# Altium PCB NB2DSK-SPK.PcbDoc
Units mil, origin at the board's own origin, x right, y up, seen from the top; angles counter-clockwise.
Board outline 10614.17 x 2937.01 mil, 2 copper layers (Top Layer, Bottom Layer); 27 components, 35 nets, 104 pads, 52 vias.
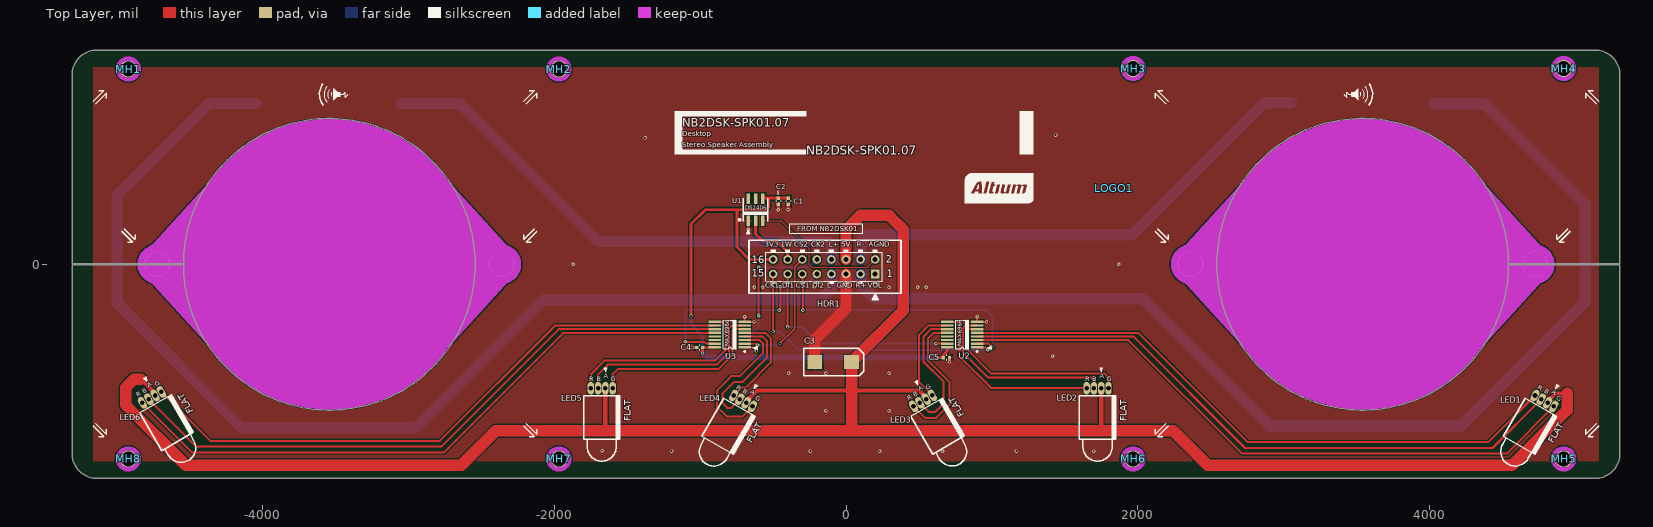
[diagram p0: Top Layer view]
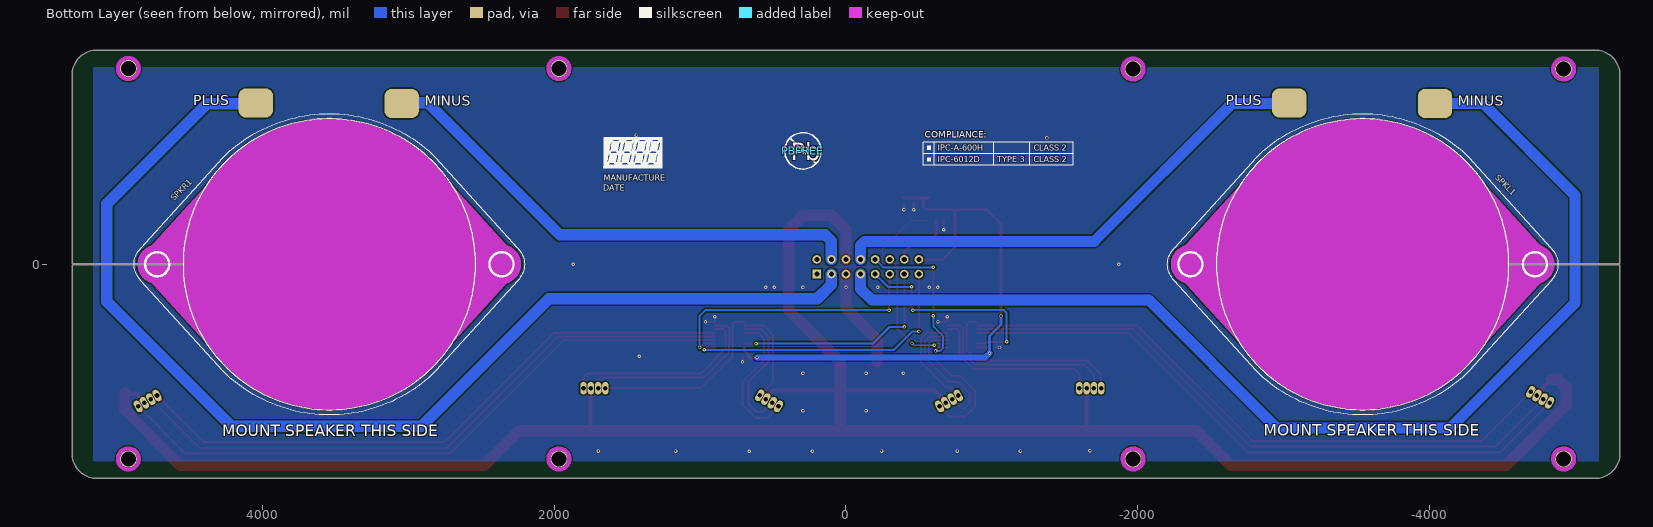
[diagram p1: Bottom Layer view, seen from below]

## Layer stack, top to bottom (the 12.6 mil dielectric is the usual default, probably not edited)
Top Layer: signal copper 1.4
Dielectric: core 12.6, FR-4, Dk 4.8
Bottom Layer: signal copper 1.4

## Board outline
-5137.8,-1468.51 cw(c-5137.8,-1299.21) -5307.09,-1299.21 -5307.09,-3.94 -4543.31,-3.94 -4543.3,-3.9 ccw(c-3543.31,0) -4543.3,3.92 -4543.31,3.92 -5307.09,3.92 -5307.09,1299.21 cw(c-5137.8,1299.21) -5137.8,1468.5 5137.8,1468.5 cw(c5137.8,1299.21) 5307.09,1299.21 5307.09,3.92 4543.31,3.92 4543.3,3.92 ccw(c3543.31,0.02) 4543.3,-3.9 4543.31,-3.94 5307.09,-3.94 5307.09,-1299.21 cw(c5137.8,-1299.21) 5137.8,-1468.51

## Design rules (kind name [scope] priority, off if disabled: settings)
Clearance "Pad-Pad Clearance Same Net" [IsPad vs IsPad] p1 off: gap=3.94
Clearance "General Clearance" [All] p2: gap=5
ComponentClearance [All] p1 off: gap=7.87 collisioncheckmode=3 verticalgap=10 showdistances=FALSE
DiffPairsRouting [All] p1: maxlimit=5 minlimit=5 mostfreqgap=5 maxuncoupledlength=200
FabricationTestPointUsage TestPointUsage [All] p1 off: valid=0 allowmultiple=FALSE
FabricationTestpoint Testpoint [All] p1 off: side=3 testpointundercomponent=TRUE minsize=40 maxsize=100 preferedsize=60 minholesize=0 maxholesize=40 preferedholesize=32 testpointgrid=1 allowsidetop=TRUE allowsidebottom=TRUE usegrid=TRUE gridtolerance=0.01
HoleSize [All] p1: absolutevalues=TRUE maxlimit=204.72 minlimit=7.87 maxpercent=80.000 minpercent=20.000
MatchedLengths DiffPair_MatchedLengths [(IsDifferentialPair And (Name = 'DIFF_RX1'))] p1: tolerance=1000 checknetsindiffpair=TRUE checkdiffpairvsdiffpair=TRUE checkothers=TRUE
MinimumAnnularRing [All] p1: minimumring=4.72
PlaneClearance [All] p1: clearance=11.81
PlaneConnect [All] p1: planeconnectstyle=Direct reliefexpansion=19.68 reliefentries=4 reliefconductorwidth=9.84 reliefairgap=9.84
PolygonConnect PolygonConnect_Tight [IsVia] p1: connectstyle=Direct reliefconductorwidth=11.81 reliefentries=4 polygonreliefangle="90 Angle"
PolygonConnect "PolygonConnect - Heatsink" [(HasFootprint('TO-263') AND InNet('VCCINT'))] p2: connectstyle=Relief reliefconductorwidth=10 reliefentries=4 polygonreliefangle="90 Angle"
PolygonConnect [IsPAD] p3: connectstyle=Relief reliefconductorwidth=11.81 reliefentries=4 polygonreliefangle="90 Angle"
RoutingLayers [All] p1: top layer_v5=FALSE bottom layer_v5=FALSE
RoutingVias [All] p1: holewidth=11.81 width=23.62 viastyle="Through Hole" minholewidth=11.81 minwidth=23.62 maxholewidth=19.68 maxwidth=35.43
ShortCircuit ShortCircuit_1 [Net = 'No Net' vs Net = 'No Net'] p1: allowed=TRUE
ShortCircuit [All] p2: allowed=FALSE
SilkscreenOverComponentPads [All] p1: minsilkscreentomaskgap=10
SolderMaskExpansion SolderMaskExpansion_Vias [IsVia] p1: expansion=-25.59
SolderMaskExpansion [All] p2: expansion=2.01
Width [All] p1: maxlimit=98.43 minlimit=5 preferedwidth=5
18 further rules are at their usual default settings.

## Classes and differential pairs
component class U_1WB_DS2406_EPROM: C1 C2 U1
differential pair class DIFF_IN: DIFF_RX0 DIFF_RX1 DIFF_RX2 DIFF_RX3
differential pair class DIFF_OUT: DIFF_TX0 DIFF_TX1 DIFF_TX2 DIFF_TX3

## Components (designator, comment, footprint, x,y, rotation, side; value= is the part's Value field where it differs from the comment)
C1 "0.1uF 16V" CAPC1005-STAR -395.25,433.09 r90 top
C2 "10nF 16V" CAPC1005-STAR -464.13,433.07 r270 top
C3 "220uF 10V" CAPC7343-STAR -88.59,-669.32 r180 top (schematic designator C1)
C4 "0.1uF 16V" CAPC1005-STAR -1003.94,-570.87 r0 top locked (schematic designator C2)
C5 "0.1uF 16V" CAPC1005-STAR 688.98,-639.76 r180 top locked (schematic designator C3)
HDR1 "2x8 Header 0.1\" Staight" HDR2X8 200,-67.01 r180 top
LED1 "RGB LED 5MM" LED-RGB-5MM-RA 4725,-900 r330 top locked
LED2 "RGB LED 5MM" LED-RGB-5MM-RA 1650,-850 r0 top locked
LED3 "RGB LED 5MM" LED-RGB-5MM-RA 462.6,-974.41 r30 top locked
LED4 "RGB LED 5MM" LED-RGB-5MM-RA -770.87,-900 r330 top locked
LED5 "RGB LED 5MM" LED-RGB-5MM-RA -1750,-850 r0 top locked
LED6 "RGB LED 5MM" LED-RGB-5MM-RA -4825,-950 r30 top locked
LOGO1 "Altium" Logo-Altium 1840.64,521.68 r0 top
MH1 "MOUNTING_HOLE_2MM" MOUNTING_HOLE_2MM#1 -4921.26,1338.58 r0 top locked
MH2 "MOUNTING_HOLE_2MM" MOUNTING_HOLE_2MM#2 -1968.5,1338.58 r0 top locked
MH3 "MOUNTING_HOLE_2MM" MOUNTING_HOLE_2MM#2 1968.5,1342.52 r0 top locked
MH4 "MOUNTING_HOLE_2MM" MOUNTING_HOLE_2MM#2 4921.26,1342.52 r0 top locked
MH5 "MOUNTING_HOLE_2MM" MOUNTING_HOLE_2MM#2 4921.26,-1334.65 r0 top locked
MH6 "MOUNTING_HOLE_2MM" MOUNTING_HOLE_2MM#2 1968.5,-1334.65 r0 top locked
MH7 "MOUNTING_HOLE_2MM" MOUNTING_HOLE_2MM#2 -1968.5,-1334.65 r0 top locked
MH8 "MOUNTING_HOLE_2MM" MOUNTING_HOLE_2MM#2 -4921.26,-1334.65 r0 top locked
PBFREE "" LEAD_FREE_S 295.29,777.6 r180 bottom
SPKL1 "SPEAKER_4R_50_60" SPEAKER_4R_50_60 -3543.31,0 r180 bottom locked (schematic designator SPKL)
SPKR1 "SPEAKER_4R_50_60" SPEAKER_4R_50_60 3543.31,0 r180 bottom locked (schematic designator SPKR)
U1 "DS2406" TSOC6 -620.08,374.02 r0 top locked
U2 "MAX6966, QSOP16" QSOP16 797.24,-482.28 r90 top locked (schematic designator U1)
U3 "MAX6966, QSOP16" QSOP16 -797.24,-482.28 r90 top locked (schematic designator U2)

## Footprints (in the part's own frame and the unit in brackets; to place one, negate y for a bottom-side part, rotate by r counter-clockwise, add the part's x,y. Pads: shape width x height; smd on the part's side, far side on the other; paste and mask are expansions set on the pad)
CAPC1005-STAR [mm] "Chip Capacitor 1005"
  rect 0.6x0.6 smd mask+0.038: 1(-0.525,0) 2(0.525,0)
  silkscreen extent -0.05,-0.38 0.05,0.38, body extent -0.57,-0.3 0.57,0.3, height 0.2
CAPC7343-STAR [mm] "Capcacitor SMD 7.3 x 4.3mm (D-Case)"
  rect 2.6x2.4 smd: 1(-3.202,0.007) 2(3.198,0.007)
  silkscreen extent -5.33,-2.39 5.08,2.41, body extent -3.5,-2.03 3.51,2.04, height 1.75
HDR2X8 [mm]
  rect 1.5x1.5 hole 0.9 mask+0.038: 1(0,0)
  round 1.5 hole 0.9 mask+0.038: 2(0,-2.54) 3(2.54,0) 4(2.54,-2.54) 5(5.08,0) 6(5.08,-2.54) 7(7.62,0) 8(7.62,-2.54) 9(10.16,0) 10(10.16,-2.54) 11(12.7,0) 12(12.7,-2.54) 13(15.24,0) 14(15.24,-2.54) 15(17.78,0) 16(17.78,-2.54)
  silkscreen extent -1.27,-3.81 19.05,1.27, body extent -1.27,-3.78 19.05,1.24, height 4.95
LEAD_FREE_S [mil]
  silkscreen extent -125,-125 125,125
LED-RGB-5MM-RA [mil] "LED RGB Right Angle 5mm"
  oval 44x85 hole 31.5 paste+0 mask+0: A(100,0) B(50,0) G(150,0) R(0,0)
  silkscreen extent -50,-500 200,-50
Logo-Altium [mil]
  silkscreen extent -1025,-99 -556,102
MOUNTING_HOLE_2MM#1 [mm] "Non-plated mounting hole for 2mm screw"
  round 3 hole 2.65 unplated mask+0: MOUNT(0,0)
  Top Layer keep-out circle w0.6: c0,0 r1.8
  Bottom Layer keep-out circle w0.6: c0,0 r1.8
  Keep-Out Layer circle w0.6: c0,0 r1.9
MOUNTING_HOLE_2MM#2 [mm] "Non-plated mounting hole for 2mm screw"
  round 3 hole 2.65 unplated paste+0 mask+0: MOUNT(0,0)
  Top Layer keep-out circle w0.6: c0,0 r1.8
  Bottom Layer keep-out circle w0.6: c0,0 r1.8
  Keep-Out Layer circle w0.6: c0,0 r1.9
QSOP16 [mm]
  rect 0.4x2.2 smd mask+0.038: 1(-2.222,-2.6) 2(-1.587,-2.6) 3(-0.952,-2.6) 4(-0.317,-2.6) 5(0.318,-2.6) 6(0.953,-2.6) 7(1.588,-2.6) 8(2.222,-2.6) 9(2.222,2.6) 10(1.587,2.6) 11(0.952,2.6) 12(0.317,2.6) 13(-0.318,2.6) 14(-0.953,2.6) 15(-1.588,2.6) 16(-2.222,2.6)
  silkscreen extent -3.1,-2.73 2.5,1.1, body extent -2.74,-2.4 2.67,2.64, height 0.73
SPEAKER_4R_50_60 [mm] "Header For Connecting Speakers to NB2"
  rrect50% 6x5.08 smd mask+0.038: 1(-12.8,28.1) 2(12.6,28)
  round 4.5 hole 4.2 unplated: M1(-30,0) M1(30,0)
  Keep-Out Layer circle w26: c0,0 r12.3
  Keep-Out Layer lines w8: 13.6,-16.4 28.5,0 13.6,16.4 ; -13.6,-16.4 -28.5,0 -13.6,16.4
  silkscreen extent -34,-26.25 34,26.25, body extent -33.96,-26 33.96,26, height 31.5
TSOC6 [mil]
  rect 25x71 smd mask+1.5: 1(-50,-75) 2(0,-75) 3(50,-75) 4(50,75) 5(0,75) 6(-50,75)
  silkscreen extent -115,-80 85,80, body extent -79,-90 84,91, height 40

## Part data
C1 C4 C5: library part D-101-0080, "Capacitor, Ceramic, 0.1uF 10% 16V 0402 (1005) X7R"
C2: library part D-101-0077, "Capacitor, Ceramic, 10nF 10% 16V 0402 (1005) X7R"
C3: library part D-101-0088, "Capacitor, Tantalum, 220uF 10% 10V MCCT-D (7343-31)"
HDR1: library part D-300-0041, "Header, BOX 2x8, 0.1\", Straight, Raised"
LED1 LED2 LED3 LED4 LED5 LED6: library part D-153-0001, "LED, RGB, 5mm, 540R2GBC-CA, Common Anode"
LOGO1: library part D-000-0003, "Altium Logo for PCB"
MH1 MH2 MH3 MH4 MH5 MH6 MH7 MH8: "2mm Diameter Mounting Hole"
SPKL1 SPKR1: library part D-003-0001, "Speaker, 4 Omh 3W 50mm Cone 60mm Body"
U1: library part D-263-0002, "Dual Addressable Switch Plus 1KB Memory"
U2 U3: library part D-243-0001, "MAX6966, 10 port Constant Current LED Driver, SPI"

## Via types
v1: diameter 23.62, hole 11.81, Top Layer to Bottom Layer, 51 vias
v2: diameter 28, hole 12, Top Layer to Bottom Layer, 1 vias

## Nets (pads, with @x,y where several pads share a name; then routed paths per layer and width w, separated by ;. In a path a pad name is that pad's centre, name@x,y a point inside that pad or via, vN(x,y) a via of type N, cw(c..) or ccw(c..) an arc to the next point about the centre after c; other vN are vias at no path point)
3V3: C1.2 C2.1 C4.2 C5.2 HDR1.16 U1.4 U2.16 U3.16 | length 4139.7
  Top Layer w13.78: C4.2@-982.19,-569.78 U3.16
  Top Layer w19.68: v1(-1062.99,-354.33) -1062.99,275.59 -964.57,374.02 -748,374.02 ; v1(-984.25,-610.24) -984.25,-571.85 C4.2 ; -748.03,344.49 -748.03,118.11 -662.91,32.99 HDR1.16 ; -748,344.52 -748,374.02 ; U1.4@-569.88,453.74 C2.1 C1.2 C1.2@-392.72,453.74 ; -531.5,452.76 -531.5,393.7 -551.18,374.02 -748,374.02 ; v1(610.24,-639.76) C5.2 669.29,-638.78 669.29,-620.08 694.88,-594.49 U2.16@694.88,-572.5
  Bottom Layer w19.68: v1(-1062.99,-354.33) -1062.99,-413.39 -984.25,-492.13 v1(-984.25,-610.24)
  Bottom Layer w39.37: v1(-984.25,-610.24) -954.72,-639.76 v1(610.24,-639.76)
5V0: C3.1 HDR1.6 LED1.A LED2.A LED3.A LED4.A LED5.A LED6.A | length 15166.7
  Top Layer w29.53: -4842.52,-787.4 -4835.72,-787.4 -4744.09,-879.03 LED6.A@-4744.09,-885.83 ; -1650,-1138.19 LED5.A ; LED4.A -684.26,-940.17 -610.24,-866.14 39.37,-866.14 502.04,-866.14 549.2,-913.31 LED3.A ; 1750,-1139.76 LED2.A ; LED1.A 4811.6,-938.9 4864.67,-885.83 4945.02,-885.83
  Top Layer w78.74: -4835.72,-787.4 -4881.89,-787.4 -4940.94,-846.46 -4940.94,-964.57 -4527.56,-1377.95 -2637.8,-1377.95 -2401.57,-1141.73 39.37,-1141.73 ; HDR1.6 0,236.22 98.43,334.65 295.28,334.65 393.7,236.22 393.7,-314.96 39.37,-669.29 39.37,-669.6 39.37,-866.14 39.37,-1141.73 ; 4945.02,-885.83 4945.02,-999.86 4566.93,-1377.95 2480.31,-1377.95 2244.09,-1141.73 39.37,-1141.73
CS1_N: HDR1.11 U2.2 | length 1897.1
  Top Layer w13.78: HDR1.11 -300,-152.76 -295.28,-157.48 v1(-295.28,-314.96) ; U2.2 977.85,-544.78 v1(1003.94,-570.87)
  Bottom Layer w13.78: v1(-295.28,-314.96) 964.57,-314.96 1003.94,-354.33 v1(1003.94,-570.87)
CS2_N: HDR1.12 U3.2 | length 890.9
  Top Layer w9.84: U3.2 -616.63,-544.78 v1(-606.3,-555.12) ; v1(-452.76,-543.31) -350.39,-440.94 -350.39,-17.4 HDR1.12
  Bottom Layer w9.84: v1(-606.3,-555.12) -464.57,-555.12 v1(-452.76,-543.31)
DC_VOL: HDR1.1
DIN1: HDR1.13 U2.15 | length 1504.7
  Top Layer w13.78: v1(-400,-430) HDR1.13 ; v1(616.63,-544.78) U2.15
  Bottom Layer w13.78: v1(-400,-430) -298.35,-430 -185.35,-543 v1@616.63,-543
DIN2: HDR1.9 U3.15 | length 1506.8
  Top Layer w13.78: v1(-1102.36,-531.5) -971.46,-531.5 -958.17,-544.78 U3.15 ; v1(-459,-314.96) -450,-305.96 v1(-450,-155)
  Bottom Layer w13.78: v1(-1102.36,-531.5) -1102.36,-334.65 -1082.68,-314.96 v1(-459,-314.96) ; v1(-450,-155) -287.99,-155 HDR1.9
GND: C1.1 C2.2 C3.2 C4.1 C5.1 HDR1.5 U1.1 U2.8 U3.8 | length 1084.1
  Top Layer w13.78: v1(-694.88,-360.24) U3.8 v1(-631,-394.78) ; v1(899.61,-360.24) U2.8 v1(963.48,-394.78)
  Top Layer w19.68: v1(-1053.15,-570.87) C4.1 ; v1(-670.08,237.01) U1.1 ; v1(-464.13,374.02) C2.2 ; v1(-397.2,374.02) C1.1@-397.2,412.4 ; v1(709.65,-668.31) C5.1
  Top Layer w78.74: C3.2 -214.49,-516.49 -0.05,-302.05 v1(0,-157.48) HDR1.5
  other v1: 230.02,-1283 663.09,-1283 -1195.98,-1281 -762.91,-1281 -244,-1281 1169,-1281 1698.91,-1281 -1673,-1278 -137.8,-1003.94 295.28,-1003.94 -393.7,-748.03 -137.8,-748.03 295.28,-748.03 1417.32,-629.92 -629.92,-157.48 -570.87,-157.48 -216.54,-157.48 295.28,-157.48 492.13,-157.48 551.18,-157.48 -1870.08,0 1870.08,0 -1377.95,866.14 1437.01,885.83
L_MINUS: HDR1.7 SPKL1.2 | length 7705.2
  Bottom Layer w75: SPKL1.2@-4045.28,1102.36 -4370.08,1102.36 -5000,472.44 -5000,-265.75 -4143.7,-1122.05 -2952.76,-1122.05 -2076.77,-246.06 -177.17,-246.06 -100,-168.9 HDR1.7
L_PLUS: HDR1.8 SPKL1.1 | length 3450.7
  Bottom Layer w75: SPKL1.1@-3051.18,1102.36 -3039.37,1102.36 -2647.64,1102.36 -1702.76,157.48 -127.95,157.48 -100,129.53 HDR1.8
NetLED1_B: LED1.B U2.4 | length 4324.3
  Top Layer w13.78: U2.4 1971.16,-494.78 2736.22,-1259.84 4433.46,-1259.84 LED1.B
NetLED1_G: LED1.G U2.3 | length 4412.4
  Top Layer w13.78: U2.3 1937.11,-519.78 2716.54,-1299.21 4530.69,-1299.21 LED1.G
NetLED1_R: LED1.R U2.5 | length 4269.1
  Top Layer w13.78: U2.5 2005.22,-469.78 2755.91,-1220.47 4404.53,-1220.47 LED1.R
NetLED2_B: LED2.B U2.7 | length 1304.7
  Top Layer w13.78: U2.7 820.37,-419.78 801.34,-438.82 801.34,-604.49 974.41,-777.56 1683.07,-777.56 1700,-794.49 LED2.B
NetLED2_G: LED2.G U2.6 | length 1329.8
  Top Layer w13.78: U2.6 838.48,-444.78 826.77,-456.5 826.77,-580.71 994.09,-748.03 1771.65,-748.03 1800,-776.38 LED2.G
NetLED2_R: LED2.R U2.9 | length 1275
  Top Layer w13.78: U2.9 766.63,-394.78 777.56,-405.71 777.56,-629.92 997.64,-850 LED2.R
NetLED3_B: LED3.B U2.11 | length 915
  Top Layer w13.78: LED3.B 570.27,-1013.78 610.24,-1013.78 669.29,-954.72 669.29,-807.09 531.5,-669.29 531.5,-495.87 582.58,-444.78 U2.11
NetLED3_G: LED3.G U2.10 | length 673.4
  Top Layer w13.78: LED3.G 501.97,-808.88 501.97,-482.28 564.47,-419.78 U2.10
NetLED3_R: LED3.R U2.12 | length 980.5
  Top Layer w13.78: LED3.R 541.34,-1053.15 620.08,-1053.15 708.66,-964.57 708.66,-807.09 561.02,-659.45 561.02,-511.81 603.05,-469.78 U2.12
NetLED4_B: LED4.B U3.4 | length 908.3
  Top Layer w13.78: -787.4,-984.25 -814.96,-984.25 -846.46,-952.76 -846.46,-885.83 -767.72,-807.09 -708.66,-807.09 -543.31,-641.73 -543.31,-525 -573.52,-494.78 U3.4 ; -787.11,-984.54 LED4.B
NetLED4_G: LED4.G U3.3 | length 1033.9
  Top Layer w13.78: U3.3 -592.42,-519.78 -570.87,-541.34 -570.87,-610.24 -728.35,-767.72 -787.4,-767.72 -885.83,-866.14 -885.83,-976.38 -818.9,-1043.31 -709.27,-1043.31 LED4.G
NetLED4_R: LED4.R U3.5 | length 709.3
  Top Layer w13.78: LED4.R -717.32,-846.46 -688.98,-846.46 -515.75,-673.23 -515.75,-507.87 -553.84,-469.78 U3.5
NetLED5_B: LED5.B U3.7 | length 1336.9
  Top Layer w13.78: LED5.B -1700,-755.12 -1633.86,-688.98 -885.83,-688.98 -802.99,-606.14 -802.99,-438.82 -783.96,-419.78 U3.7
NetLED5_G: LED5.G U3.6 | length 1225.3
  Top Layer w13.78: LED5.G -1600,-753.54 -1564.96,-718.5 -875.98,-718.5 -777.56,-620.08 -777.56,-456.5 -765.85,-444.78 U3.6
NetLED5_R: LED5.R U3.9 | length 1342.3
  Top Layer w13.78: LED5.R -1750,-755.91 -1653.54,-659.45 -895.67,-659.45 -826.77,-590.55 -826.77,-415.55 -847.54,-394.78 U3.9
NetLED6_B: LED6.B U3.11 | length 4350.2
  Top Layer w13.78: LED6.B -4456.7,-1250 -2775.59,-1250 -1970.37,-444.78 U3.11
NetLED6_G: LED6.G U3.10 | length 4262.1
  Top Layer w13.78: LED6.G -4359.47,-1210.63 -2785.43,-1210.63 -1994.59,-419.78 U3.10
NetLED6_R: LED6.R U3.12 | length 4405.4
  Top Layer w13.78: LED6.R -4485.63,-1289.37 -2755.91,-1289.37 -1936.32,-469.78 U3.12
ONE_WIRE: HDR1.14 U1.2 | length 414.8
  Top Layer w19.68: U1.2 -620.08,206.69 -570.87,157.48 -472.44,157.48 -400,85.04 HDR1.14
ONE_WIRE.PIO2: U1.6
PIO1: HDR1.2 U1.3 | length 988.5
  Top Layer w6: U1.3 -444.69,299.02 -251.97,106.3 -251.97,-3.94 -236.22,-19.69 147.32,-19.69
  Top Layer w7: 147.32,-19.69 HDR1.2
R_MINUS: HDR1.4 SPKR1.2 | length 3473.5
  Bottom Layer w78.74: HDR1.4 100,159.06 141.73,200.79 1960.63,200.79 2866.14,1106.3 3047.24,1106.3 SPKR1.2@3055.12,1106.3
R_PLUS: HDR1.3 SPKR1.1 | length 7787.1
  Bottom Layer w78.74: HDR1.3 100,-139.37 196.85,-236.22 2037.4,-236.22 2913.39,-1112.2 4212.6,-1112.2 5068.9,-255.91 5068.9,413.39 4379.92,1102.36 4047.24,1102.36 SPKR1.1@4035.43,1102.36
SCLK1: HDR1.15 U2.1 | length 1997.9
  Top Layer w13.78: v1@-500,-460.63 HDR1.15 ; U2.1 955.61,-569.78 v1(972.44,-586.61)
  Bottom Layer w13.78: v1(-500,-461) -455,-461 -329.39,-586.61 v1(972.44,-586.61)
SCLK2: HDR1.10 U3.1 | length 1153.4
  Top Layer w13.78: U3.1 -638.88,-569.78 v1(-614.17,-594.49) ; v1(-599,-353) v1(-599,-21)
  Bottom Layer w13.78: v1(-614.17,-594.49) -645.51,-594.49 -666,-574 -666,-493 -599,-426 v1(-599,-353) ; v1(-599,-21) -253.99,-21 HDR1.10
pads on no net: MH1.MOUNT MH2.MOUNT MH3.MOUNT MH4.MOUNT MH5.MOUNT MH6.MOUNT MH7.MOUNT MH8.MOUNT SPKL1.M1 SPKR1.M1 U1.5 U2.13 U2.14 U3.13 U3.14
copper on no net:
  other v2: 4921.26,1342.52

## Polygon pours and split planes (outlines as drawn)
GND on Top Layer "MAIN_TL" (solid, remove dead copper, pour order 1000): -5055.12,1350 5161.42,1350 5161.42,-1350 -5161.42,-1350 -5161.42,1350
GND on Bottom Layer "GND" (solid, remove dead copper, pour order 1000): -5161.42,1350.39 -5161.42,-1350.39 5161.42,-1350.39 5161.42,1350.39

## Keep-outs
Keep-Out Layer:
  circle w78.74: c4724.41,0 r95.47
  circle w78.74: c2362.2,0 r95.47
  circle w78.74: c-2362.2,0 r95.47
  circle w78.74: c-4724.41,0 r95.47

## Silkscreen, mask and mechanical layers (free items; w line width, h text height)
Top Overlay:
  drawing of 237 lines, arcs and shapes, not listed
  text "NB2DSK-SPK01.07" at -1122.05,921.54 h98.43
  text "Desktop" at -1122.05,863.54 h60
  text "Stereo Speaker Assembly" at -1122.05,787.56 h60
  text "NB2DSK-SPK01.07" at -271.85,751.54 h60
  text "DS2406" at -691.73,372.62 h28
  text "FROM NB2DSK01" at -333.49,228.02 h35
  text "3V3" at -555.94,104.88 h60
  text "1W" at -448,105 h60
  text "CS2" at -356,105 h60
  text "CK2" at -240,105 h60
  text "L+" at -120,105 h60
  text "5V" at -31.81,104.88 h60
  text "R-" at 72.87,104.88 h60
  text "AGND" at 154.47,105 h60
  text "L-" at -128.5,-175 h60
  text "CK1" at -555,-176 h60
  text "DI1" at -437,-176 h60
  text "CS1" at -346,-176 h60
  text "DI2" at -230.75,-175.63 h60
  text "GND" at -64.52,-175.98 h60
  text "R+" at 65.47,-175.98 h60
  text "VOL" at 148.49,-175.98 h60
  text "MAX6966" at -799.21,-562.99 h28 r90
  text "MAX6966" at 795.28,-562.99 h28 r90
Bottom Overlay:
  drawing of 1069 lines, arcs and shapes, not listed
  text "COMPLIANCE:" at -538.92,868.05 h45
  text "CLASS 2" at -1288.92,778.05 h40
  text "IPC-A-600H" at -628.92,778.05 h40
  text "CLASS 2" at -1288.92,698.05 h40
  text "TYPE 3" at -1038.92,698.05 h40
  text "IPC-6012D" at -628.92,698.05 h40
  text "MANUFACTURE" at 1662.27,572.58 h40
  text "DATE" at 1663.37,505.78 h40
Top Solder:
  circle w78.74: c4724.41,0 r95.47
  circle w78.74: c2362.2,0 r95.47
  circle w78.74: c-2362.2,0 r95.47
  circle w78.74: c-4724.41,0 r95.47
  circle w78.74: c-4921.26,-1334.65 r49.21
  circle w78.74: c-1968.5,-1334.65 r49.21
  circle w78.74: c1968.5,-1330.71 r49.21
  circle w78.74: c4921.26,-1330.71 r49.21
  circle w78.74: c4921.26,1342.52 r49.21
  circle w78.74: c1968.5,1342.52 r49.21
  circle w78.74: c-1968.5,1338.58 r49.21
  circle w78.74: c-4921.26,1338.58 r49.21
Bottom Solder:
  circle w100: c3546.1,-2.68 r1005.06
  circle w100: c-3540.51,-2.68 r1005.06
  lines w78.74: -5281.45,-0.01 cw(c-5307.09,-3.94) -5281.15,-3.94 -5281.15,-1299.21 ccw(c-5137.8,-1299.21) -5137.8,-1442.57 0,-1442.57 5137.8,-1442.57 ccw(c5137.8,-1299.21) 5281.15,-1299.21 5281.15,-3.94 cw(c5307.09,-3.94) 5281.45,-0.01 cw(c5307.09,3.92) 5281.15,3.92 5281.15,1299.21 ccw(c5137.8,1299.21) 5137.8,1442.57 0,1442.57 -5137.8,1442.57 ccw(c-5137.8,1299.21) -5281.15,1299.21 -5281.15,3.92 cw(c-5307.09,3.92) -5281.45,-0.01
  lines w100: -4785.78,-114.63 cw(c-4662.56,-2.68) -4785.75,109.3 -4364.07,573.44 cw(c-3540.51,-2.68) -4189.14,765.07 cw(c-4075.94,642.99) -4174.97,776.82 cw(c-3540.51,-2.68) -2906.06,776.82 cw(c-3005.08,642.99) -2891.89,765.07 ; -4785.78,109.27 ccw(c-4662.56,-2.68) -4785.75,-114.66 -4364.07,-578.79 ccw(c-3540.51,-2.68) -4189.14,-770.42 ccw(c-4075.94,-648.35) -4174.97,-782.18 ccw(c-3540.51,-2.68) -2906.06,-782.18 ccw(c-3005.08,-648.35) -2891.89,-770.42 ccw(c-3540.51,-2.68) -2716.96,-578.79 -2295.27,-114.66 ccw(c-2418.46,-2.68) -2251.98,-2.68 ; -2716.96,573.44 -2295.27,109.3 cw(c-2418.46,-2.68) -2251.98,-2.68 ; -2295.25,-114.63 ccw(c-2418.46,-2.68) -2251.98,-2.68 ; -2295.25,109.27 cw(c-2418.46,-2.68) -2251.98,-2.68 ; 2300.84,-114.63 cw(c2424.06,-2.68) 2300.86,109.3 2722.55,573.44 cw(c3546.1,-2.68) 2897.48,765.07 cw(c3010.67,642.99) 2911.65,776.82 cw(c3546.1,-2.68) 4180.56,776.82 cw(c4081.54,642.99) 4194.73,765.07 ; 2300.84,109.27 ccw(c2424.06,-2.68) 2300.86,-114.66 2722.55,-578.79 ccw(c3546.1,-2.68) 2897.48,-770.42 ccw(c3010.67,-648.35) 2911.65,-782.18 ccw(c3546.1,-2.68) 4180.56,-782.18 ccw(c4081.54,-648.35) 4194.73,-770.42 ccw(c3546.1,-2.68) 4369.66,-578.79 4791.34,-114.66 ccw(c4668.15,-2.68) 4834.63,-2.68 ; 4369.66,573.44 4791.34,109.3 cw(c4668.15,-2.68) 4834.63,-2.68 ; 4791.37,-114.63 ccw(c4668.15,-2.68) 4834.63,-2.68 ; 4791.37,109.27 cw(c4668.15,-2.68) 4834.63,-2.68
  lines w200: -4568.51,269.14 ccw(c-4171.75,-0.49) -4558.37,-284.47 ; -2522.34,-284.47 ccw(c-2908.96,-0.49) -2512.2,269.14 ; 2518.11,269.14 ccw(c2914.86,-0.49) 2528.24,-284.47 ; 4562.31,-284.47 ccw(c4175.69,-0.49) 4572.44,269.14
1. PCB Boundary:
  lines w7.87: -4543.31,-3.94 -5307.09,-3.94 -5307.09,-1299.21 ccw(c-5137.8,-1299.21) -5137.8,-1468.51 0,-1468.51 5137.8,-1468.51 ccw(c5137.8,-1299.21) 5307.09,-1299.21 5307.09,-3.94 4543.31,-3.94 ; -4543.31,3.92 -5307.09,3.92 -5307.09,1299.21 cw(c-5137.8,1299.21) -5137.8,1468.5 0,1468.5 5137.8,1468.5 cw(c5137.8,1299.21) 5307.09,1299.21 5307.09,3.92 4543.31,3.92 ; -4543.3,-3.9 ccw(c-3543.31,0) -4543.3,3.92 ; 4543.3,-3.9 cw(c3543.31,0.02) 4543.3,3.92
4. Dimensions:
  circle w1023.62: c-3543.31,0 r492.13
  circle w1023.62: c3543.31,0 r492.13
6. FabNotes:
  drawing of 719 lines, arcs and shapes, not listed
  text "NB2DSK-SPK01" at 8487.8,4749.89 h45
  text "DESIGN INFORMATION" at 6273.68,4749.11 h45
  text "BOARD NAME:" at 7753.68,4749.11 h45
  text "BOARD TECHNOLOGY" at 6273.68,4649.11 h45
  text "BOARD SIZE (REFER ALSO PROFILING INFORMATION)" at 8173.68,4649.11 h45
  text "10" at 6357.18,4562.93 h45
  text "269.6mm" at 8280.77,4559.58 h45
  text "10" at 6895.69,4556.12 h45
  text "74.6mm" at 9186.28,4555.65 h45
  text "10" at 7445.69,4551.12 h45
  text "X" at 8908.68,4529.11 h45
  text "(MIN. TRACK/   PADS  /   CLEARANCE     IN 0.001'')" at 6213.68,4449.11 h45
  text "MINIMUM ANNULAR RING 0.05MM (0.002'') EXTERNAL PER IPC-2221 CLASS 3 LEVEL C AND IS TH" at 6273.68,4349.11 h45
  text "MANUFACTURING REGISTRATION ALLOWANCE" at 6273.68,4259.11 h45
  text "LAND SIZE CALCULATION MINIMUM - NOMINAL HOLE SIZE + 0.508MM (0.020'')" at 6273.68,4149.11 h45
  text "X" at 7753.68,3979.11 h45
  text "X" at 8453.68,3979.11 h45
  text "CIRCUIT TYPE:" at 6273.68,3969.11 h45
  text "SS" at 7173.68,3969.11 h45
  text "DS" at 7873.68,3969.11 h45
  text "PTH" at 8573.68,3969.11 h45
  text "ML" at 9003.68,3969.11 h45
  text "No. of Layers" at 9273.68,3969.11 h45
  text "FINGER CONNECTOR DIM PER:" at 6273.68,3849.11 h45
  text "AS SHOWN" at 9273.68,3849.11 h45
  text "No. OFF TOTAL" at 6933.68,3739.11 h45
  text "ONE SIDE" at 8573.68,3739.11 h45
  text "BOTH SIDES" at 9273.68,3729.11 h45
  text "X" at 7753.68,3629.11 h45
  text "X" at 6600,3625 h45
  text "VIAS:" at 6273.68,3624.11 h45
  text "NONE" at 6723.68,3624.11 h45
  text "FEED THRU'" at 7173.68,3624.11 h45
  text "TENTED" at 7873.68,3624.11 h45
  text "BURIED LAYER SEQUENCE" at 8573.68,3624.11 h45
  text "X" at 7048.68,3509.11 h45
  text "UNIQUE DRILL" at 7173.68,3504.11 h45
  text "2 SIZE" at 7873.68,3504.11 h45
  text "BLIND LAYER SEQUENCE" at 8573.68,3504.11 h45
  text "Layer Stack Manager (PCB)" at 7668.68,3414.11 h45
  text "X" at 9153.68,3414.11 h45
  text "AS SHOWN" at 9273.68,3414.11 h45
  text "LAYER CONSTRUCTION PER:" at 6273.68,3409.11 h45
  text "Altium Designer 6.6" at 9267.33,3304.41 h45
  text "ARTWORK:" at 6273.68,3299.11 h45
  text "MANUAL" at 7173.68,3299.11 h45
  text "DIGITISED" at 7873.68,3299.11 h45
  text "X" at 8453.68,3299.11 h45
  text "CAD" at 8573.68,3299.11 h45
  text "TYPE" at 9003.68,3299.11 h45
  text "ARTWORK/PATTERN MASTER LIST" at 6273.68,3114.11 h45
  text "DESCRIPTION" at 6323.68,3019.11 h45
  text "DRAWING No./CAD FILE REF." at 7058.68,3019.11 h45
  text "LAYER NAME" at 8683.68,3019.11 h45
  text "GERBER FILE REF" at 9500.69,3016.12 h45
  text "PCB FILE" at 6263.68,2919.11 h45
  text "NB2DSK-SPK.PCBDOC" at 7065.2,2916.85 h45
  text "PcbDoc" at 8295.69,2916.12 h45
  text "Top Paste Mask" at 8617.7,2819.11 h45
  text "NB2DSK-SPK" at 7070.2,2816.85 h45
  text "GTP" at 8342.13,2817.17 h45
  text "GTP" at 10295.69,2816.12 h45
  text "GERBER FILE" at 6263.68,2814.11 h45
  text "GTO" at 8342.13,2718.74 h45
  text "GTO" at 10293.68,2718.13 h45
  text "NB2DSK-SPK" at 7070.2,2716.85 h45
  text "Top Overlay" at 8617.7,2717.1 h45
  text "GERBER FILE" at 6263.68,2714.11 h45
  text "Top Solder Mask" at 8617.7,2621.12 h45
  text "GTS" at 8342.13,2620.32 h45
  text "NB2DSK-SPK" at 7070.2,2616.85 h45
  text "GTS" at 10295.69,2616.12 h45
  text "GERBER FILE" at 6263.68,2614.11 h45
  text "TOP LAYER" at 8617.7,2519.11 h45
  text "NB2DSK-SPK" at 7070.2,2516.85 h45
  text "GTL" at 10295.69,2516.12 h45
  text "GERBER FILE" at 6263.68,2514.11 h45
  text "GTL" at 8342.13,2514.02 h45
  text "NB2DSK-SPK" at 7070.2,2221.85 h45
  text "BOTTOM LAYER" at 8602.7,2219.11 h45
  text "GBL" at 8327.13,2216.23 h45
  text "GBL" at 10280.69,2216.12 h45
  text "GERBER FILE" at 6248.68,2214.11 h45
  text "GBS" at 8327.13,2121.74 h45
  text "Bottom Solder Mask" at 8602.7,2121.12 h45
  text "NB2DSK-SPK" at 7070.2,2116.85 h45
  text "GBS" at 10280.69,2116.12 h45
  text "GERBER FILE" at 6248.68,2114.11 h45
  text "GBO" at 8327.13,2019.37 h45
  text "Bottom Overlay" at 8602.7,2019.11 h45
  text "NB2DSK-SPK" at 7070.2,2016.85 h45
  text "GBO" at 10280.69,2016.12 h45
  text "GERBER FILE" at 6248.68,2014.11 h45
  text "GBP" at 10280.69,1921.12 h45
  text "Bottom Paste Mask" at 8602.69,1919.11 h45
  text "NB2DSK-SPK" at 7070.2,1916.85 h45
  text "GBP" at 8327.13,1917.17 h45
  text "GERBER FILE" at 6243.68,1914.11 h45
  text "APERTURE LIST" at 6263.68,1119.37 h45
  text "APR" at 8335.06,1116.38 h45
  text "DRILL REPORT" at 6263.68,1019.37 h45
  text "DRR" at 8335.06,1016.38 h45
  text "DRILL FILE" at 6253.21,916.73 h45
  text "DRL" at 8330.14,911.06 h45
  text "TXT" at 8324.07,816.34 h45
  text "EXCELLON DRILL" at 6250.25,813.38 h45
  text "MATERIAL:" at 6273.68,608.45 h45
  text "GLASS FIBRE EPOXY RESIN NEMA GRADE FR4-08 (IPC-4101) - WITH TG170" at 7283.68,598.45 h45
  text "X" at 7178.68,593.45 h45
  text "THICKNESS:" at 6583.68,483.45 h45
  text "0.8mm" at 7283.68,483.45 h45
  text "1.2mm" at 7978.68,483.45 h45
  text "1.6mm" at 8673.67,483.47 h45
  text "2.4mm" at 9373.68,483.45 h45
  text "3.2mm" at 10073.68,483.45 h45
  text "X" at 8578.68,478.45 h45
  text "2" at 8427.15,369.48 h45
  text "TOLERANCE:" at 6578.68,363.45 h45
  text "OTHER +/-" at 9373.68,363.45 h45
  text "X" at 7178.68,358.45 h45
  text "IN A/W IPC-D-300G CLASS" at 7305.18,355.58 h45
  text "2" at 8427.15,247.43 h45
  text "BOW & TWIST:" at 6578.17,243.45 h45
  text "AS SHOWN" at 9378.68,238.45 h45
  text "IN A/W IPC-D-300G CLASS" at 7305.18,235.58 h45
  text "X" at 7178.68,233.45 h45
  text "COPPER THICKNESS (FINISHED)" at 6482.26,125.38 h45
  text "18um" at 7283.68,23.45 h45
  text "35um" at 8348.68,23.45 h45
  text "70um" at 9383.68,23.45 h45
  text "OUTER:" at 6624,19.08 h45
  text "X" at 8240.69,15.46 h45
  text "ROUTED HOLE" at -4075,-50 h100
  text "ROUTED HOLE" at 3075,-50 h100
  text "18um" at 7283.68,-96.55 h45
  text "35um" at 8348.68,-96.55 h45
  text "70um" at 9383.68,-96.55 h45
  text "INNER SIGNAL:" at 6624,-99.03 h45
  text "X" at 8238.68,-104.54 h45
  text "INNER PWR:" at 6624,-217.14 h45
  text "18um" at 7283.68,-216.55 h45
  text "35um" at 8348.68,-216.55 h45
  text "70um" at 9383.68,-216.55 h45
  text "X" at 8243.68,-221.55 h45
  text "STRUCTURE:" at 6273.68,-336.55 h45
  text "REFER" at 7283.68,-336.55 h45
  text "AS PER DRAWING No." at 7278.68,-461.55 h45
  text "AS SHOWN" at 9378.68,-461.55 h45
  text "X" at 9278.68,-466.55 h45
  text "DRILLING:" at 6273.68,-571.55 h45
  text "COMPONENT SIDE" at 7283.68,-661.55 h45
  text "SOLDER SIDE" at 8338.68,-661.55 h45
  text "VIEWED FROM:" at 6549.19,-669.89 h45
  text "X" at 7178.68,-671.55 h45
  text "REFERENCE:" at 6558.68,-781.55 h45
  text "AS SHOWN" at 7278.68,-786.55 h45
  text "PATTERN MASTER LIST" at 8343.68,-786.55 h45
  text "X" at 9278.68,-786.55 h45
  text "NC_DRILL FILES" at 9378.68,-786.55 h45
  text "X" at 7178.68,-791.55 h45
  text "20um" at 8348.68,-901.55 h45
  text "PTH MINIMUM COPPER THICKNESS:" at 6561,-906.12 h45
  text "X" at 8243.68,-906.55 h45
  text "OTHER" at 9378.68,-906.55 h45
  text "NPTH:" at 6557.07,-1020.29 h45
  text "TENTED" at 7278.68,-1026.55 h45
  text "X" at 8243.68,-1026.55 h45
  text "PADS REMOVED" at 8343.68,-1026.55 h45
  text "REMOVE PADS" at 9378.68,-1026.55 h45
  text "X" at 7178.68,-1031.55 h45
  text "2nd DRILL" at 7278.68,-1146.55 h45
  text "BOTH" at 8343.68,-1146.55 h45
  text "AS SHOWN" at 8828.68,-1146.55 h45
  text "NONE" at 9378.68,-1146.55 h45
  text "BOARD FINISH:" at 6273.68,-1261.55 h45
  text "X" at 7178.68,-1266.55 h45
  text "ETCHING" at 7278.68,-1266.55 h45
  text "REFER PATTERN MASTER LIST" at 8343.68,-1266.55 h45
  text "LEGEND / SCREEN PRINT:" at 6525.57,-1382.49 h45
  text "NONE" at 7612.26,-1382.18 h45
  text "COMPONENT" at 8343.56,-1383.56 h45
  text "SOLDER" at 9379.98,-1386.12 h45
  text "X" at 8243.56,-1388.56 h45
  text "X" at 9279.98,-1391.12 h45
  text "WHITE" at 7281.56,-1496.35 h45
  text "COLOUR:" at 6757.85,-1500.6 h45
  text "X" at 7181.56,-1501.35 h45
  text "YELLOW" at 8343.68,-1506.55 h45
  text "OTHER" at 9378.68,-1506.55 h45
  text "SOLDER RESIST:" at 6517.7,-1626.59 h45
  text "X" at 7178.68,-1626.55 h45
  text "LIQUID PHOTOIMAGEABLE" at 7278.68,-1626.55 h45
  text "SCREEN PRINT" at 8828.68,-1626.55 h45
  text "FINISH:" at 6769.67,-1744.7 h45
  text "MATTE" at 7278.68,-1746.55 h45
  text "GLOSS" at 7778.68,-1746.55 h45
  text "X" at 7673.68,-1751.55 h45
  text "COLOUR:" at 6757.85,-1862.81 h45
  text "BLACK" at 7278.68,-1866.55 h45
  text "GREEN" at 7778.68,-1866.55 h45
  text "YELLOW" at 8343.68,-1866.55 h45
  text "BLUE" at 8828.68,-1866.55 h45
  text "OTHER" at 9378.68,-1866.55 h45
  text "X" at 7173.68,-1871.55 h45
  text "TRACK FINISH:" at 6273.68,-1981.55 h45
  text "SELECTIVE SOLDER (HASL)" at 7278.68,-1986.55 h45
  text "REFLOW SOLDER" at 8828.68,-1986.55 h45
  text "0.1um - 0.2um ELECTROLESS GOLD OVER 3um NICKEL" at 7281.48,-2099.03 h45
  text "X" at 7179.11,-2102.97 h45
  text "IMMERSION GOLD" at 7278.68,-2226.55 h45
  text "OTHER" at 8828.68,-2226.55 h45
  text "BOARD EDGES ARE ROUNDED AS SHOWN" at -2210,-2325 h150
  text "EDGE BOARD" at 6273.68,-2341.55 h45
  text "1.3um HARD GOLD OVER 5um     NICKEL / TIN-NICKEL" at 7278.68,-2346.55 h45
  text "CONTACTS:" at 6273.68,-2426.55 h45
  text "HARD FINISH GOLDE PLATE" at 7278.68,-2466.55 h45
  text "OTHER" at 8828.68,-2466.55 h45
  text "AS SHOWN" at 7278.68,-2586.55 h45
  text "REFER" at 8828.68,-2586.55 h45
  text "PROFILING:" at 6273.68,-2706.55 h45
  text "AS DIMENSIONED, MEASURED AND CUT FROM SPECIFIED DATUM." at 7278.68,-2706.55 h45
  text "X" at 7178.68,-2711.55 h45
  text "REFER PCB BLANK DWG No." at 7283.68,-2821.55 h45
  text "USE PROFILE / ROUTE TAPE SUPPLIED (REFER PATTERN MASTER LIST)" at 7283.68,-2941.55 h45
  text "SQUARE CUT" at 7283.68,-3061.55 h45
  text "X" at 7873.68,-3061.55 h45
  text "N.C. ROUTE" at 7983.68,-3061.55 h45
  text "V. SCORE" at 8683.68,-3061.55 h45
  text "BLANK" at 9383.68,-3061.55 h45
  text "ACCEPTABILITY:" at 6273.68,-3166.55 h45
  text "MATERIALS AND WORKMANSHIP FOR ALL PRINTED WIRING BOARDS TO MEET" at 7148.68,-3171.55 h45
  text "OR EXCEED THE REQUIREMENTS OF:" at 7148.68,-3281.55 h45
  text "NANOBOARD NB2DSK-SPK" at -2271.32,-3376.55 h250
  text "IPC-6011/12 AND IPC-A-600E" at 7288.68,-3386.55 h45
  text "1" at 8688.68,-3386.55 h45
  text "2" at 9038.68,-3386.55 h45
  text "3" at 9388.92,-3388.99 h45
  text "X" at 8933.68,-3391.55 h45
  text "X" at 7183.68,-3396.55 h45
  text "UL CERTIFICATION" at 7288.68,-3506.55 h45
  text "AUSTEL" at 8688.68,-3506.55 h45
  text "X" at 7183.68,-3511.55 h45
  text "ML-P-55110F GRP" at 7268.68,-3626.55 h45
  text "A" at 7988.68,-3626.55 h45
  text "B" at 8338.68,-3626.55 h45
  text "AS2546" at 8688.68,-3626.55 h45
  text "OTHER" at 9388.68,-3626.55 h45
  text "ADDITIONAL REQUIREMENTS:" at 6265.73,-3756.51 h45
  text "REV.07" at -666.32,-3781.55 h250
  text "NONE" at 7287.34,-3858.01 h45
  text "SAMPLE PLAN" at 7987.34,-3858.01 h45
  text "MIL-P-55110E SERIAL Nos. PER ORDER" at 8766.08,-3858.01 h45
  text "X" at 7181.08,-3858.6 h45
  text "MICROSECTION:" at 6470.45,-3862.81 h45
  text "NONE" at 7291.08,-3983.52 h45
  text "CERTIFICATION:" at 6466.52,-3988.79 h45
  text "A" at 8764.27,-3992.69 h45
  text "MIL-P-55110E GRP" at 7983.01,-3994.66 h45
  text "B" at 8975.53,-3995.8 h45
  text "1" at 9947.97,-3999.74 h45
  text "2" at 10159.23,-4002.85 h45
  text "3" at 10375.77,-4002.85 h45
  text "IPC CLASS:" at 9380.65,-4006.47 h45
  text "RoHS Compliant" at 7291.08,-4109.5 h45
  text "X" at 7181.08,-4114.5 h45
  text "X" at 7879.43,-4118.01 h45
  text "QUALITY RELEASE REPORT" at 7983.01,-4120.64 h45
  text "OTHER" at 9384.74,-4122.61 h45
  text "NONE" at 7288.92,-4235.96 h45
  text "REQUIRED (100% NETS & PADS)" at 7988.92,-4235.96 h45
  text "ELECTRICAL TEST:" at 6466.52,-4240.76 h45
  text "X" at 7883.92,-4240.96 h45
  text "PER ORDER" at 9388.68,-4241.55 h45
  text "2 SIDES" at 8751.75,-4361.43 h45
  text "MIN. PITCH" at 9384.98,-4361.43 h45
  text "0.6mm" at 9919.98,-4361.43 h45
  text "NONE" at 7288.92,-4361.94 h45
  text "1 SIDE" at 7983.92,-4361.94 h45
  text "SURFACE MOUNT:" at 6462.58,-4366.75 h45
  text "X" at 7875,-4375 h45
  text "FOIL" at 8767.66,-4485.56 h45
  text "NONE" at 7988.92,-4489.5 h45
  text "LEGEND" at 9111.36,-4489.5 h45
  text "REFER" at 9583.92,-4489.5 h45
  text "Bottom Overlay" at 9903.76,-4488.95 h45
  text "X" at 9005.41,-4491.04 h45
  text "X" at 9477.85,-4491.04 h45
  text "MANUFACTURER'S ID/LOGO:" at 6462.58,-4500.6 h45
  text "NONE" at 8769.67,-4610.84 h45
  text "ISO9001/AS3901" at 7989.7,-4617.85 h45
  text "MANUFACTURER'S ACCREDITATION:" at 6462.58,-4622.65 h45
  text "X" at 7884.7,-4622.85 h45
  text "PACKAGING AND HANDLING:" at 6462.58,-4732.89 h45
  text "REFER" at 8767.66,-4741.31 h45
  text "PER ORDER" at 7988.92,-4745.25 h45
  text "X" at 7883.92,-4755.25 h45
  text "Notes" at 6163.37,-5047.85 h45
  text "1. All dimensions are in mm. The router cutter diameter is 2.4mm." at 6229.11,-5277.38 h45
Drill Drawing:
  text ".Legend" at -4838.57,3070.86 h60

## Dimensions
5137.8,-1468.51 to 5137.8,1468.5 on 6. FabNotes
-5307.09,-3.94 to 5307.09,-1299.21 on 6. FabNotes
5137.8,-1468.51 to 4921.26,-1334.65 on 6. FabNotes
-5307.09,3.92 to -4543.31,3.92 on 6. FabNotes
4724.41,0 to 5307.09,-1299.21 on 6. FabNotes
2362.2,0 to 4724.41,0 on 6. FabNotes
-2362.2,0 to 2362.2,0 on 6. FabNotes
-4724.41,0 to -2362.2,0 on 6. FabNotes
-5307.09,-1299.21 to -4724.41,0 on 6. FabNotes
4921.26,-1334.65 to 5307.09,-1299.21 on 6. FabNotes
1968.5,-1334.65 to 4921.26,-1334.65 on 6. FabNotes
-1968.5,-1334.65 to 1968.5,-1334.65 on 6. FabNotes
-4921.26,-1334.65 to -1968.5,-1334.65 on 6. FabNotes
-5307.09,-1299.21 to -4921.26,-1334.65 on 6. FabNotes
3543.31,1000.02 to 5137.8,1468.5 on 6. FabNotes
3543.31,-999.98 to 3543.31,1000.02 on 6. FabNotes
5137.8,-1468.51 to 3543.31,-999.98 on 6. FabNotes
-4724.41,0 to -5137.8,1468.5 on 6. FabNotes
-5137.8,-1468.51 to -4724.41,0 on 6. FabNotes
4543.3,3.92 to 5307.09,3.92 on 6. FabNotes
2543.31,0.02 to 4543.3,3.92 on 6. FabNotes
-2543.31,0 to 2543.31,0.02 on 6. FabNotes
-4543.31,3.92 to -2543.31,0 on 6. FabNotes
-5307.09,1299.21 to -5307.09,3.92 on 6. FabNotes
-1909.45,1397.64 to -1771.65,1586.61 on 6. FabNotes
-3543.31,0 to -2470.49,-456.43 on 6. FabNotes
-2275.36,63.63 to -2050.96,173.87 on 6. FabNotes
5137.8,1299.21 to 5402.38,1563.79 on 6. FabNotes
